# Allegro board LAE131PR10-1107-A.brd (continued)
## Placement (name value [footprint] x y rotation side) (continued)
PC106  -  [C_0805]  227.23 28.96 90 bottom
PC107  -  [C_0805]  227.21 28.96 90 top
PC108  -  [C_0805]  223.8 28.96 90 bottom
PC109  -  [C_0805]  225.52 28.96 90 bottom
PC110  -  [C_0805]  225.49 28.96 90 top
PC111  -  [C_0603]  232.5 21.71 0 bottom
PC112  -  [C_0603]  230.23 26.03 90 top
PC113  -  [C_0402]  235.83 22.95 270 bottom
PC114  -  [C_0603]  39.54 48.04 180 bottom
PC115  -  [C_0402]  38.09 45.33 0 bottom
PC116  -  [C_0402]  38.09 45.33 0 top
PC117  -  [C_0805]  37.12 42.51 180 top
PC118  -  [C_0805]  37.09 42.56 180 bottom
PC119  -  [C_0603]  32.13 49.03 180 bottom
PC120  -  [C_0805]  39.12 55.42 0 bottom
PC121  -  [C_0805]  39.17 53.71 0 top
PC122  -  [C_0805]  39.12 55.42 0 top
PC123  -  [C_0805]  39.14 57.17 0 bottom
PC124  -  [C_0805]  39.17 53.71 0 bottom
PC125  -  [C_0603]  36.76 47.54 0 top
PC126  -  [C_0603]  32.16 47.82 180 bottom
PC127  -  [C_0402]  32.29 45.93 180 bottom
PC128  -  [C_0402]  238.44 23.73 270 bottom
PC129  -  [C_0805]  223.78 28.96 90 top
PC130  -  [C_0805]  39.14 57.17 0 top
PC200  -  [C_0805]  35.18 38.6 0 bottom
PC201  -  [C_0805]  35.19 39.25 0 top
PC202  -  [C_0402]  35.08 40.56 0 top
PC203  -  [C_0402]  30.36 38.59 270 bottom
PC204  -  [C_0603]  30.3 26.46 270 bottom
PC205  -  [C_0603]  30.69 31.73 0 bottom
PC206  -  [C_0402]  32.81 34.08 180 bottom
PC207  -  [C_0402]  32.81 34.97 180 bottom
PC208  -  [C_0402]  31.98 35.86 0 bottom
PC209  -  [C_0603]  39.13 27.73 0 bottom
PC210  -  [C_0603]  39.11 25.28 0 bottom
PC211  -  [C_0603]  39.11 25.29 0 top
PC212  -  [C_0603]  39.11 26.5 0 top
PC213  -  [C_0603]  39.13 26.5 0 bottom
PC214  -  [C_0603]  38.23 32.39 0 bottom
PC216  -  [C_0402]  39.59 23.25 0 top
PC217  -  [C_0402]  39.59 24.14 0 top
PC218  -  [C_0402]  38.15 33.27 270 top
PC219  -  [C_0603]  38.23 33.61 0 bottom
PC221  -  [C_0402]  39.08 39.54 0 top
PC222  -  [C_0402]  40.07 35.74 270 top
PC301  -  [C_0402]  181.04 103.31 180 bottom
PC302  -  [C_0603]  181.66 95.83 90 top
PC303  -  [C_0402]  181.04 102.42 180 bottom
PC304  -  [C_0603]  185.8 100.94 180 top
PC305  -  [C_0603]  181.73 101.36 270 bottom
PC306  -  [C_0603]  181.74 101.38 270 top
PC307  -  [C_0402]  188.48 98.34 180 bottom
PC308  -  [C_0603]  178.09 98.43 90 top
PC309  -  [C_0603]  179.95 98.42 90 bottom
PC310  -  [C_0603]  179.97 98.42 90 top
PC311  -  [C_0603]  178.18 98.42 90 bottom
PC312  -  [C_0603]  186.06 102.55 90 bottom
PC313  -  [C_0603]  185.8 98.46 270 top
PC401  -  [C_0402]  181 113.01 180 bottom
PC402  -  [C_0402]  189.94 109.68 0 bottom
PC403  -  [C_0603]  188.18 107.02 180 bottom
PC404  -  [C_0603]  189.04 110.84 180 top
PC406  -  [C_0603]  181.87 107.65 0 bottom
PC407  -  [C_0603]  181.89 106.41 0 bottom
PC408  -  [C_0402]  188.19 105.96 180 bottom
PC409  -  [C_0402]  188.74 111.92 180 top
PC410  -  [C_0402]  186.95 114.18 180 bottom
PC411  -  [C_0402]  177.7 113.32 0 bottom
PC412  -  [C_0603]  175.74 113.28 270 bottom
PC413  -  [C_0603]  175.74 113.28 270 top
PC415  -  [C_0603]  174.16 106.9 0 bottom
PC416  -  [C_0603]  174.13 105.63 0 bottom
PC417  -  [C_0402]  176.82 113.29 270 bottom
PC418  -  [C_0402]  176.82 113.29 270 top
PC419  -  [C_0402]  168.98 106.72 90 bottom
PC420  -  [C_0402]  168.66 111.87 270 bottom
PC422  -  [C_0603]  181.85 108.88 0 bottom
PC424  -  [C_0603]  174.16 108.21 0 bottom
PC501  -  [C_0603]  159.84 101.85 180 bottom
PC502  -  [C_0603]  166.55 103.78 0 bottom
PC503  -  [C_0402]  168.91 99.47 90 bottom
PC504  -  [C_0603]  159.84 103.14 180 bottom
PC505  -  [C_0402]  164.84 99.07 270 bottom
PC506  -  [C_0402]  163.92 99.65 90 bottom
PC513  -  [C_0402]  199.9 22.8 0 top
PC514  -  [C_0603]  199.81 25.75 180 top
PC515  -  [C_0402]  194.17 23.48 270 top
PC516  -  [C_0603]  195.21 25.85 0 top
PC601  -  [C_0402]  55.12 78.1 180 top
PC602  -  [C_0402]  49.15 71.21 0 bottom
PC603  -  [C_0603]  50.17 72.36 0 bottom
PC604  -  [C_0603]  48.38 73.46 90 bottom
PC605  -  [C_0402]  51.93 66.24 270 top
PC606  -  [C_D]  68.07 79.65 90 bottom
PC608  -  [C_0805]  74.67 89.6 270 bottom
PC611  -  [C_0603]  73.29 89.85 180 top
PC612  -  [C_0805]  74.67 89.6 270 top
PC613  -  [C_0402]  50.34 69.79 270 bottom
PC614  -  [C_0402]  53.47 69.56 270 bottom
PC616  -  [C_0402]  51.61 69.41 270 bottom
PC617  -  [C_0402]  49.89 65.3 0 bottom
PC618  -  [C_0402]  48.01 65.12 0 top
PC619  -  [C_0402]  48.01 64.1 0 top
PC620  -  [C_0402]  49.02 65.32 180 bottom
PC621  -  [C_0402]  46.99 64.23 90 top
PC622  -  [C_0603]  77.6 87.72 180 top
PC624  -  [C_0402]  53.6 67.01 270 bottom
PC625  -  [C_0402]  54.74 70.33 0 bottom
PC626  -  [C_0402]  52.68 67.01 270 bottom
PC627  -  [C_0402]  53.71 66.2 90 top
PC628  -  [C_0402]  52.38 74.62 270 bottom
PC629  -  [C_0402]  55.23 73.92 270 bottom
PC630  -  [C_0402]  56.95 75.55 90 top
PC631  -  [C_0402]  50.55 73.75 0 bottom
PC632  -  [C_0402]  51.18 76.24 90 top
PC633  -  [C_0402]  51.17 76.31 90 bottom
PC635  -  [C_0402]  57.91 67.54 180 top
PC636  -  [C_0402]  54.78 71.2 0 bottom
PC637  -  [C_0402]  49.39 76.31 90 bottom
PC638  -  [C_0402]  57.35 68.46 90 top
PC639  -  [C_0402]  57.89 72.89 0 top
PC640  -  [C_0402]  53.28 77.59 180 top
PC641  -  [C_0402]  50.87 66.17 180 bottom
PC642  -  [C_0402]  56.94 76.45 0 bottom
PC643  -  [C_0402]  53.27 74.62 270 bottom
PC644  -  [C_0402]  49.41 78.2 180 bottom
PC645  -  [C_0402]  79 79.8 180 top
PC646  -  [C_0402]  56.94 75.56 0 bottom
PC647  -  [C_0402]  59.73 72.02 270 top
PC649  -  [C_0402]  54.23 76.68 0 bottom
PC650  -  [C_0402]  52.49 76.7 0 bottom
PC651  -  [C_0402]  58.74 73.78 180 top
PC652  -  [C_0402]  52.49 77.59 0 bottom
PC653  -  [C_0402]  56.95 73.77 90 top
PC654  -  [C_0402]  58.74 74.67 180 top
PC655  -  [C_0603]  76.46 76.31 90 top
PC656  -  [C_0805]  69.41 78.05 90 top
PC657  -  [C_0805]  71.31 78.05 90 top
PC658  -  [C_0805]  71.31 78.05 90 bottom
PC659  -  [C_0402]  64.84 77.29 270 top
PC660  -  [C_0402]  63.95 77.29 270 top
PC661  -  [C_0402]  77.4 84.8 0 top
PC662  -  [C_0603]  69.62 84.08 270 top
PC663  -  [C_0603]  54.66 67.53 0 bottom
PC664  -  [C_0805]  56.68 60.93 0 bottom
PC665  -  [C_0805]  56.68 62.71 0 bottom
PC669  -  [C_0402]  62.37 68.98 0 bottom
PC670  -  [C_0603]  64.39 61.18 180 bottom
PC671  -  [C_0603]  62.79 75.17 0 top
PC672  -  [C_0805]  65.47 70.69 0 top
PC673  -  [C_0805]  65.47 70.69 0 bottom
PC677  -  [C_0402]  70.68 76.93 0 bottom
PC678  -  [C_0603]  69.26 72.17 90 top
PC679  -  [C_0402]  63.57 71.15 270 bottom
PC680  -  [C_0402]  62.15 77.28 270 top
PC681  -  [C_0402]  55.12 64.43 270 bottom
PC682  -  [C_0805]  61.69 77.88 180 bottom
PC683  -  [C_0805]  61.77 72.38 270 bottom
PC684  -  [C_0805]  60.02 72.41 270 bottom
PC685  -  [C_0402]  72.99 86.38 0 bottom
PC686  -  [C_0402]  63.04 77.29 270 top
PC687  -  [C_0402]  54.1 64.43 270 bottom
PC688  -  [C_0402]  64.45 71.15 270 bottom
PC902  -  [C_0402]  50.94 80.49 270 top
PC903  -  [C_0402]  50.56 80.41 270 bottom
PC904  -  [C_0805]  56.37 78.8 0 top
PC905  -  [C_0805]  56.37 78.8 0 bottom
PC906  -  [C_0805]  56.39 80.54 0 top
PC909  -  [C_B2]  45.27 79.69 0 bottom
PC910  -  [C_B2]  45.38 76.49 0 bottom
PC911  -  [C_0805]  53.52 78.89 180 bottom
PC913  -  [C_0805]  67.95 91.66 0 bottom
PC914  -  [C_0805]  67.95 91.66 0 top
PC915  -  [C_0805]  69.7 93.47 0 bottom
PC916  -  [C_0805]  67.95 88.17 0 top
PC917  -  [C_0805]  67.92 89.95 0 top
PC918  -  [C_0805]  67.95 88.19 0 bottom
PC919  -  [C_0805]  65.22 92.68 180 top
PC920  -  [C_0805]  67.93 89.91 0 bottom
PC925  -  [C_0402]  58.73 88.36 0 bottom
PC926  -  [C_0402]  57.41 89.34 180 bottom
PC927  -  [C_0402]  60.51 88.36 270 bottom
PC928  -  [C_0402]  69.65 94.82 0 bottom
PC929  -  [C_0402]  69.65 94.82 0 top
PC930  -  [C_0603]  63.88 87.2 90 bottom
PC931  -  [C_0603]  55.7 91.62 0 bottom
PC932  -  [C_0402]  65.85 88.29 180 bottom
PC933  -  [C_0402]  57.34 91.8 180 top
PC934  -  [C_0603]  66.9 91.5 180 bottom
PC935  -  [C_0805]  202.69 39.21 90 bottom
PC936  -  [C_0805]  200.92 39.21 90 bottom
PC937  -  [C_0402]  208.28 42.04 180 bottom
PC938  -  [C_0402]  56.95 96.19 90 bottom
PC939  -  [C_0402]  64.92 93.43 0 bottom
PC940  -  [C_0603]  52.52 89.82 0 top
PC941  -  [C_0603]  60.67 77.6 180 top
PC942  -  [C_0402]  64.94 94.35 0 bottom
PC943  -  [C_0402]  60.69 96.09 180 bottom
PC944  -  [C_0402]  60.69 96.97 180 bottom
PC945  -  [C_0402]  64.76 95.41 0 bottom
PC946  -  [C_0402]  64.75 96.36 90 bottom
PC947  -  [C_0402]  61.45 95.64 90 top
PC949  -  [C_0402]  31.8 73.73 0 top
PC950  -  [C_0402]  62.96 96.89 270 bottom
PC951  -  [C_B2]  45.25 82.88 0 bottom
PC1001  -  [C_0603]  123.13 81.82 270 top
PC1002  -  [C_0603]  120.7 75.66 90 top
PC1003  -  [C_0603]  86.69 84.27 270 bottom
PC1004  -  [C_0603]  121.92 75.66 90 top
PC1005  -  [C_0603]  89.1 84.27 270 bottom
PC1006  -  [C_0603]  125.54 75.66 90 top
PC1007  -  [C_0603]  87.9 84.3 270 top
PC1008  -  [C_0603]  85.46 84.27 270 top
PC1009  -  [C_0603]  124.86 95.23 90 top
PC1010  -  [C_0603]  120.73 79.44 270 top
PC1011  -  [C_0603]  88.85 81.18 270 bottom
PC1012  -  [C_0603]  86.44 81.17 270 bottom
PC1013  -  [C_0603]  124.33 75.66 90 top
PC1014  -  [C_0603]  115.38 77.31 90 top
PC1015  -  [C_0603]  118.26 72.71 0 top
PC1016  -  [C_0603]  112.17 72.74 0 top
PC1017  -  [C_0603]  86.87 77.77 270 bottom
PC1018  -  [C_0603]  115.67 72.76 0 top
PC1019  -  [C_0603]  113.22 80.61 180 top
PC1020  -  [C_0603]  117.81 81.07 270 top
PC1021  -  [C_0603]  116.61 81.07 270 top
PC1022  -  [C_0603]  104.88 80.33 90 top
PC1023  -  [C_0603]  114.15 74.95 90 top
PC1024  -  [C_0603]  116.59 77.33 90 top
PC1025  -  [C_0603]  89.22 77.76 270 top
PC1026  -  [C_0603]  115.38 81.06 270 top
PC1027  -  [C_0603]  105.23 82.72 90 top
PC1028  -  [C_0603]  115.38 74.96 90 top
PC1029  -  [C_0603]  104.02 82.71 90 top
PC1030  -  [C_0201]  119.77 77.08 180 top
PC1031  -  [C_0201]  126.95 81.14 0 top
PC1032  -  [C_0201]  126.95 80.57 0 top
PC1033  -  [C_0201]  126.64 84.19 0 top
PC1034  -  [C_0201]  119.79 77.67 180 top
PC1035  -  [C_0201]  119.75 79.96 180 top
PC1036  -  [C_0201]  127.84 84.29 0 top
PC1037  -  [C_0201]  120.42 82.86 180 top
PC1038  -  [C_0201]  126.38 74.74 180 top
PC1039  -  [C_0201]  119.8 75.29 180 top
PC1040  -  [C_0201]  107.82 78.61 270 top
PC1041  -  [C_0201]  106.61 76.77 0 top
PC1042  -  [C_0201]  114.03 84.16 0 top
PC1043  -  [C_0201]  105.86 77.78 270 top
PC1044  -  [C_0201]  106.51 79.92 90 top
PC1045  -  [C_0201]  114.5 73.05 270 top
PC1046  -  [C_0201]  110.54 83.48 270 top
PC1047  -  [C_0201]  106.51 78.52 90 top
PC1048  -  [C_0201]  108.46 81.34 270 top
PC1049  -  [C_0201]  113.41 84.14 180 top
PC1050  -  [C_0201]  126.95 78.28 0 top
PC1051  -  [C_0201]  126.05 84.18 180 top
PC1052  -  [C_0201]  126.95 79.43 0 top
PC1053  -  [C_0201]  122 74.03 270 top
PC1054  -  [C_0201]  122.63 73.6 270 top
PC1055  -  [C_0201]  107.8 79.96 90 top
PC1056  -  [C_0201]  113.93 81.86 0 top
PC1057  -  [C_0603]  130.34 79.57 180 top
PC1058  -  [C_0603]  88.99 88.5 90 bottom
PC1059  -  [C_0603]  88.99 87.47 270 bottom
PC1060  -  [C_0603]  129.2 84.14 0 top
PC1061  -  [C_0603]  86.41 81.17 270 top
PC1062  -  [C_D3]  120.53 95.98 90 top
PC1063  -  [C_D2]  82.11 67.91 270 bottom
PC1064  -  [C_0603]  123.64 95.22 90 top
PC1065  -  [C_0603]  89.12 84.3 270 top
PC1066  -  [C_0603]  125.64 81.85 270 top
PC1067  -  [C_0603]  126.08 95.24 90 top
PC1068  -  [C_0603]  123.17 79.46 270 top
PC1069  -  [C_0603]  124.37 79.46 270 top
PC1070  -  [C_0603]  125.58 79.46 270 top
PC1071  -  [C_0603]  123.13 75.66 90 top
PC1072  -  [C_0603]  121.96 79.46 270 top
PC1073  -  [C_0603]  120.68 81.81 270 top
PC1074  -  [C_0603]  85.46 84.27 270 bottom
PC1075  -  [C_0603]  124.37 81.83 270 top
PC1076  -  [C_0603]  121.9 81.8 270 top
PC1077  -  [C_0603]  88.85 81.18 270 top
PC1078  -  [C_0603]  87.64 81.18 270 top
PC1079  -  [C_0603]  86.69 84.27 270 top
PC1080  -  [C_0603]  87.64 81.18 270 bottom
PC1081  -  [C_0603]  85.19 81.2 270 top
PC1082  -  [C_0603]  87.9 84.27 270 bottom
PC1083  -  [C_0201]  123.65 84.16 180 top
PC1084  -  [C_0201]  124.27 84.17 0 top
PC1085  -  [C_0201]  126.95 76 0 top
PC1086  -  [C_0201]  119.8 74.72 180 top
PC1087  -  [C_0201]  123.18 74.78 0 top
PC1088  -  [C_0201]  126.95 81.71 0 top
PC1089  -  [C_0201]  126.95 82.28 0 top
PC1090  -  [C_0201]  126.95 80 0 top
PC1091  -  [C_0201]  126.95 77.14 0 top
PC1092  -  [C_0201]  126.95 77.71 0 top
PC1093  -  [C_0201]  126.95 78.86 0 top
PC1094  -  [C_0201]  119.75 81.13 180 top
PC1095  -  [C_0201]  119.75 81.7 180 top
PC1096  -  [C_0201]  119.75 82.27 180 top
PC1097  -  [C_0201]  128.33 83.66 270 top
PC1098  -  [C_0201]  119.75 80.53 180 top
PC1099  -  [C_0201]  119.77 76.51 180 top
PC1100  -  [C_0603]  85.73 72.04 270 bottom
PC1101  -  [C_0603]  84.52 72.04 270 top
PC1102  -  [C_0603]  89.24 74.77 270 top
PC1103  -  [C_0603]  87 72.04 270 top
PC1125  -  [C_0201]  119.8 75.86 180 top
PC1126  -  [C_0201]  126.95 76.57 0 top
PC1127  -  [C_D3]  103.28 97.55 180 top
PC1128  -  [C_D3]  84.39 67.91 270 top
PC1129  -  [C_0603]  104.86 78.09 270 top
PC1130  -  [C_0603]  104.27 74.26 90 top
PC1131  -  [C_0603]  103.36 78.07 270 top
PC1132  -  [C_0603]  101.73 78.07 270 top
PC1133  -  [C_0603]  88.09 77.76 270 bottom
PC1134  -  [C_0603]  117.79 77.33 90 top
PC1135  -  [C_0603]  101.8 80.33 90 top
PC1136  -  [C_0603]  88.01 77.76 270 top
PC1137  -  [C_0603]  89.3 77.76 270 bottom
PC1138  -  [C_0603]  103.31 80.35 90 top
PC1139  -  [C_0603]  88.99 87.48 270 top
PC1140  -  [C_0603]  87.72 88.51 90 top
PC1141  -  [C_0603]  88.99 88.5 90 top
PC1142  -  [C_0603]  132.1 75.11 0 top
PC1143  -  [C_0603]  131.15 75.11 180 top
PC1144  -  [C_0603]  130.34 80.78 180 top
PC1145  -  [C_0603]  87.72 87.46 270 bottom
PC1146  -  [C_0603]  87.72 88.51 90 bottom
PC1147  -  [C_0201]  131.17 81.52 0 top
PC1148  -  [C_0201]  131 78.54 180 top
PC1149  -  [C_0201]  129.8 82.3 0 top
PC1150  -  [C_0201]  129.8 81.73 0 top
PC1151  -  [C_0201]  129.18 82.3 180 top
PC1152  -  [C_0201]  129.18 81.73 180 top
PC1153  -  [C_0201]  132.25 78.53 270 top
PC1164  -  [C_0201]  119.79 78.28 180 top
PC1165  -  [C_D2]  77.22 67.91 270 bottom
PC1170  -  [C_0603]  85.22 81.17 270 bottom
PC1171  -  [C_0603]  90.55 82.33 270 bottom
PC1172  -  [C_0603]  94.36 82.33 270 bottom
PC1173  -  [C_0603]  93.09 82.33 270 bottom
PC1174  -  [C_0603]  91.82 82.33 270 bottom
PC1175  -  [C_0603]  83.16 74.8 270 top
PC1176  -  [C_0603]  84.38 74.77 270 top
PC1177  -  [C_0603]  85.57 74.77 270 bottom
PC1178  -  [C_0603]  84.36 74.77 270 bottom
PC1179  -  [C_0603]  83.29 72.05 270 top
PC1180  -  [C_0603]  84.48 72.05 270 bottom
PC1181  -  [C_0603]  84.46 77.77 270 bottom
PC1182  -  [C_0603]  92.27 78.14 270 bottom
PC1183  -  [C_0603]  86.81 74.77 270 top
PC1184  -  [C_0603]  88.28 72.03 270 top
PC1185  -  [C_0603]  91 78.14 270 bottom
PC1186  -  [C_0603]  88.01 74.77 270 bottom
PC1187  -  [C_0603]  88.28 72.02 270 bottom
PC1188  -  [C_0603]  85.6 74.77 270 top
PC1189  -  [C_0603]  85.65 77.77 270 bottom
PC1190  -  [C_0603]  85.73 72.04 270 top
PC1191  -  [C_0603]  83.21 72.08 270 bottom
PC1192  -  [C_0603]  86.81 77.76 270 top
PC1193  -  [C_0603]  85.6 77.76 270 top
PC1194  -  [C_0603]  88.01 74.78 270 top
PC1195  -  [C_0603]  90.97 78.11 90 top
PC1196  -  [C_0603]  93.54 78.14 270 bottom
PC1197  -  [C_0603]  86.81 74.77 270 bottom
PC1198  -  [C_0603]  87 72.04 270 bottom
PC1199  -  [C_0603]  89.22 74.77 270 bottom
PC1201  -  [C_0402]  37.72 75.3 0 top
PC1202  -  [C_0603]  46.14 104.94 270 top
PC1203  -  [C_0402]  53.79 95.79 0 top
PC1204  -  [C_0402]  48.52 75.53 0 top
PC1205  -  [C_0402]  37.92 67.82 270 top
PC1206  -  [C_0402]  39.63 66.94 0 top
PC1207  -  [C_0402]  34.43 67.8 270 top
PC1208  -  [C_0402]  17.78 98.06 180 bottom
PC1209  -  [C_0402]  24.89 99.03 270 bottom
PC1210  -  [C_0402]  53.07 105.91 270 top
PC1211  -  [C_0402]  41 71.2 180 bottom
PC1212  -  [C_0402]  38.29 72.13 270 bottom
PC1213  -  [C_0402]  40.95 72.09 180 bottom
PC1214  -  [C_0402]  42.73 71.47 270 bottom
PC1215  -  [C_0402]  13.93 93.44 180 bottom
PC1216  -  [C_0402]  41.78 69.45 0 bottom
PC1217  -  [C_0402]  37.77 91.75 0 top
PC1286  -  [C_0402]  56.95 92.63 90 bottom
PC1301  -  [C_0402]  46.08 60.72 180 top
PC1302  -  [C_0402]  45.51 57.63 180 top
PC1303  -  [C_0805]  48.73 55.28 0 top
PC1304  -  [C_0805]  48.73 53.56 0 top
PC1305  -  [C_0603]  56.45 59.11 270 top
PC1306  -  [C_0603]  58.93 59.11 270 top
PC1307  -  [C_0603]  57.72 59.11 270 top
PC1308  -  [C_0402]  46.08 61.61 180 top
PC1309  -  [C_0402]  52.33 54.79 180 top
PC1310  -  [C_0402]  51.06 61.61 90 top
PC1311  -  [C_0402]  44.93 43.71 180 top
PC1312  -  [C_0805]  46.85 42.42 0 top
PC1313  -  [C_0805]  46.85 44.14 0 top
PC1314  -  [C_0603]  57.37 50.23 270 top
PC1315  -  [C_0603]  54.89 50.24 270 top
PC1316  -  [C_0603]  56.12 50.26 270 top
PC1317  -  [C_0402]  45.51 48.57 180 top
PC1318  -  [C_0402]  45.51 49.46 180 top
PC1319  -  [C_0402]  50.94 43.47 180 top
PC1320  -  [C_0402]  48.55 50.46 90 top
PD1  -  [TVNST52302AB0_SOT523-3]  210.61 25.99 180 top
PD2  -  [TVNST52302AB0_SOT523-3]  212.64 25.99 180 top
PD3  -  [DB3J315E0L_SMINI3-F2-B3]  308.94 10.52 180 top
PD4  -  [PESD5V0U2BT_SOT23-3]  52.83 104.26 270 bottom
PD5  -  [PDS5100H-13_POWERDI5-3]  51.91 90.35 90 bottom
PD100  -  [RB520SM-30T2R_EMD2-2]  32.07 44.04 180 bottom
PD901  -  [SDMK0340L-7-F_SOD323-2]  68.48 102.6 270 bottom
PD903  -  [RB520SM-30T2R_EMD2-2]  66.72 102.53 270 bottom
PD904  -  [SDMK0340L-7-F_SOD323-2]  64.99 102.48 270 bottom
PD905  -  [BAT54CW_SOT323-3]  30.21 73.77 270 top
PD1202  -  [PDS5100H-13_POWERDI5-3]  48.87 96.09 90 top
PD1205  -  [SDMK0340L-7-F_SOD323-2]  41.09 73.89 180 bottom
PD1801  -  [BAT54CW_SOT323-3]  36.45 74.52 180 bottom
PH601  -  [R_0402]  68.22 71.1 0 bottom
PH602  -  [R_0402]  71.99 70.81 180 bottom
PH603  -  [R_0402]  74.12 76.29 180 top
PH604  -  [R_0402]  83.97 91.12 0 bottom
PH605  -  [R_0402]  73.87 78.28 180 bottom
PJP1  -  [JUMP_43X39]  128.84 109.63 270 bottom
PJP2  -  [JUMP_43X39]  130.94 97.88 90 bottom
PJP3  -  [JUMP_43X118]  142.37 103.41 0 bottom
PJP4  -  [JUMP_43X39]  165.86 60.17 0 top
PJP5  -  [JUMP_43X79]  17.29 82.04 180 top
PJP6  -  [JUMP_43X39]  25.91 74.01 180 top
PJP7  -  [JUMP_43X39]  31.69 69.83 270 top
PJP8  -  [JUMP_43X79]  18.12 58.77 0 bottom
PJP12  -  [JUMP_43X39]  70.8 114.31 270 top
PJP14  -  [JUMP_43X79]  294.66 45.43 0 top
PJP15  -  [JUMP_43X39]  298.59 18.57 180 top
PJP16  -  [JUMP_43X39]  291.38 20.6 180 top
PJP17  -  [JUMP_43X79]  299.55 21.62 0 top
PJP18  -  [JUMP_43X39]  291.38 23.07 180 top
PJP19  -  [JUMP_43X39]  308.76 31.92 45 top
PJP20  -  [JUMP_43X39]  276.04 37.81 180 top
PJP21  -  [JUMP_43X39]  276.04 40.1 180 top
PJP22  -  [JUMP_43X39]  266.45 30.45 90 top
PJP31  -  [JUMP_43X118]  30.48 17.58 90 top
PJP35  -  [JUMP_43X39]  246.57 24.67 0 top
PJP36  -  [JUMP_43X79]  296.72 62.01 180 top
PJP37  -  [JUMP_43X39]  304.29 63.9 90 top
PJP38  -  [JUMP_43X39]  198.45 31.39 270 top
PJP39  -  [JUMP_43X118]  197.97 41.28 180 top
PJP40  -  [JUMP_43X79]  288.9 83.42 90 top
PJP41  -  [JUMP_43X118]  286.46 72.15 180 top
PJP42  -  [JUMP_43X39]  166.05 69.69 90 top
PJP100  -  [JUMP_43X79]  236.73 31.7 270 bottom
PJP101  -  [JUMP_43X79]  39.88 42.94 180 bottom
PJP102  -  [JUMP_43X118]  221.97 23.95 180 top
PJP103  -  [JUMP_43X118]  38.8 59.36 90 bottom
PJP200  -  [JUMP_43X118]  40.52 28.94 90 top
PJP201  -  [JUMP_43X39]  38.47 35.35 0 bottom
PJP202  -  [JUMP_43X79]  32.7 40.32 270 bottom
PJP301  -  [JUMP_43X79]  183.45 104.27 270 bottom
PJP302  -  [JUMP_43X118]  180.5 95.13 180 bottom
PJP391  -  [JUMP_43X39]  168.39 89.63 0 bottom
PJP401  -  [JUMP_43X79]  180.23 107.65 180 bottom
PJP402  -  [JUMP_43X79]  175.21 103.8 270 bottom
PJP403  -  [JUMP_43X39]  190.44 107.85 180 bottom
PJP404  -  [JUMP_43X39]  173.67 115.49 270 bottom
PJP501  -  [JUMP_43X39]  170.13 102.89 180 bottom
PJP502  -  [JUMP_43X39]  160.68 100.19 270 bottom
PJP505  -  [JUMP_43X39]  199.52 28.23 270 top
PJP506  -  [JUMP_43X39]  193.42 24.62 90 top
PJP601  -  [JUMP_43X118]  65.95 80.34 180 top
PJP602  -  [JUMP_43X79]  62.99 74.11 90 bottom
PJP603  -  [JUMP_43X39]  77.73 91.03 90 bottom
PJP901  -  [JUMP_43X118-NPM]  53.3 84.07 270 bottom
PJP1202  -  [JUMP_43X118]  46.2 108.11 270 top
PJP1301  -  [JUMP_43X39]  44.9 59.16 0 top
PJP1302  -  [JUMP_43X79]  57.6 60.83 90 top
PJP1303  -  [JUMP_43X79]  56.12 51.88 90 top
PJP1304  -  [JUMP_43X39]  44.3 47.03 0 top
PJPDC1  -  [CVILU_CI0805M1HRC-NH_5P-T]  47.7 103.6 270 bottom
PL1  -  [TAIYO_FBMJ4516HS720NT_2P]  211.95 35.59 90 bottom
PL2  -  [TAIYO_FBMJ4516HS720NT_2P]  214.37 35.59 90 bottom
PL3  -  [MURAT_BLM15AG102SN1D_2P]  50.75 106.72 180 bottom
PL4  -  [TAIYO_FBMJ4516HS720NT_2P]  50.65 97.32 90 bottom
PL100  -  [CYNTE_PCMC063T-1R5MN_2P]  230.38 24.82 180 bottom
PL101  -  [CYNTE_PCMC063T-1R5MN_2P]  35.08 50.26 90 bottom
PL201  -  [CYNTE_PCMB063T-1R0MS_2P]  35.08 30.47 270 bottom
PL301  -  [MAG_MMD-05CZ-R68M-X2L_2P]  187.73 95.12 180 bottom
PL402  -  [MAG_MLV-FY12N1R0M-O1L_2P]  183.16 111.03 180 bottom
PL404  -  [MAG_MLV-FY12N1R0M-O1L_2P]  172.15 108.27 270 bottom
PL501  -  [MAG_MLV-FY12N1R0M-O1L_2P]  163.69 102.47 180 bottom
PL602  -  [9A_Z80_1812_2P-NPM]  67.3 80.32 180 top
PL610  -  [MAG_MMD06CZER15MG_4P]  82.52 81.35 180 bottom
PL612  -  [MAG_MMD06CZER15MG_4P]  80.52 73.75 180 bottom
PL613  -  [MAG_MMD06CZER15MG_4P]  72.39 66.01 180 bottom
PL614  -  [MAG_MMD05CZR47M_4P]  85.27 87.89 180 bottom
PL901  -  [MAGLA_MMD-05CZ-1R0M-M7L_2P]  53.34 81.43 90 bottom
PL902  -  [CYNTE_PCMB063T-1R0MS_2P]  57.79 83.18 0 bottom
PL1201  -  [5A_Z120_0805_2P]  17.69 94.83 0 bottom
PL1202  -  [5A_Z120_0805_2P]  17.69 96.49 0 bottom
PL1301  -  [MAG_MLV-FY12N1R0M-O1L_2P]  54.17 57.78 90 top
PL1302  -  [MAG_MLV-FY12N1R0M-O1L_2P]  52.71 46.77 90 top
PQ1  -  [DMN65D8LDW-7_SOT363-6]  39.98 105.38 90 top
PQ2  -  [FDV301N-G_SOT23-3]  33.16 100.85 90 top
PQ3  -  [MMST3904-7-F_SOT323-3]  29.31 102.66 0 top
PQ4  -  [AON7409_DFN8-5]  48.59 89.05 180 bottom
PQ5  -  [NTR4502PT1G_SOT23-3]  42.67 85.97 180 bottom
PQ6  -  [DMN65D8LW-7_SOT323-3]  58.65 100.95 0 bottom
PQ7  -  [DMN65D8LW-7_SOT323-3]  47.27 84.37 0 bottom
PQ8  -  [DMN65D8LW-7_SOT323-3]  30.23 106.25 180 top
PQ9  -  [AON7409_DFN8-5]  52.73 99.02 0 bottom
PQ501  -  [AON7934_DFN3X3A8-10]  76.42 89.55 0 bottom
PQ904  -  [AON6992_DFN5X6D-8-7]  66.4 84.02 90 top
PQ905  -  [AON6992_DFN5X6D-8-7]  52.72 86 270 top
PQ906  -  [AON7409_DFN8-5]  206.99 38.75 90 bottom
PQ909  -  [DMN65D8LW-7_SOT323-3]  61.62 99.8 0 bottom
PQ1201  -  [DMN65D8LDW-7_SOT363-6]  36.69 97.38 270 top
PQ1202  -  [AON7409_DFN8-5]  52.27 98.03 0 top
PQ1203  -  [NTR4502PT1G_SOT23-3]  45.16 76.53 0 top
PQ1204  -  [DMN65D8LDW-7_SOT363-6]  43.46 81.37 0 top
PQ1205  -  [DMN65D8LW-7_SOT323-3]  49.79 86.96 180 top
PQ1206  -  [AON7409_DFN8-5]  49.79 106.66 0 top
PQ1207  -  [DMN66D0LDW-7_SOT363-6]  47.06 92.03 180 top
PQ1208  -  [DMN66D0LDW-7_SOT363-6]  43.11 88.28 90 top
PQ1209  -  [DMN65D8LDW-7_SOT363-6]  45.63 72.36 270 bottom
PQ1210  -  [DMN66D0LDW-7_SOT363-6]  40.64 92.73 90 top
PQ1211  -  [DMN66D0LDW-7_SOT363-6]  42.61 91.67 0 top
PQ1212  -  [DMN65D8LW-7_SOT323-3]  42.17 73.5 90 top
PQ1213  -  [AON7409_DFN8-5]  49.65 104.8 180 top
PQ1214  -  [DMN65D8LDW-7_SOT363-6]  41.94 100.78 270 top
PQ1215  -  [NTR4502PT1G_SOT23-3]  38.1 103.45 180 top
PQ1216  -  [DMN65D8LW-7_SOT323-3]  39.37 89.37 180 bottom
PR1  -  [R_0402]  209.23 28.54 0 top
PR2  -  [R_0402]  310.78 11.28 90 top
PR3  -  [R_0402]  33.05 98.48 180 top
PR4  -  [R_0402]  29.36 98.38 90 top
PR5  -  [R_0402]  31.31 98.48 180 top
PR6  -  [R_0402]  34.04 98.52 90 top
PR7  -  [R_0402]  29.34 100.68 90 top
PR8  -  [R_0402]  28.34 105.64 0 top
PR10  -  [R_0402]  43.72 89.76 180 bottom
PR11  -  [R_0402]  45.09 87.14 270 bottom
PR12  -  [R_0402]  55.76 102.46 0 bottom
PR13  -  [R_0805]  54.13 100.97 90 bottom
PR14  -  [R_0402]  43.72 90.65 180 bottom
PR15  -  [R_0402]  35.67 109.91 0 top
PR16  -  [R_0402]  44.68 85.16 0 bottom
PR17  -  [R_0402]  39.12 107.82 0 top
PR18  -  [R_0402]  56.14 99.66 0 bottom
PR19  -  [R0402_0OHM]  41 107.03 90 top
PR20  -  [R0402_0OHM]  48.05 83.24 180 bottom
PR21  -  [R0402_0OHM]  28.92 111.2 0 top
PR22  -  [R0402_0OHM]  34.78 108.4 180 top
PR23  -  [R0402_0OHM]  33.92 109.37 0 top
PR24  -  [R_0402]  47.12 82.34 0 bottom
PR25  -  [R0402_0OHM]  36.59 110.82 180 top
PR26  -  [R0402_0OHM]  33.25 106.38 0 top
PR27  -  [R_0402]  34.16 107.25 180 top
PR28  -  [R_0402]  31.98 106.6 90 top
PR29  -  [R0402_0OHM]  31.98 108.43 0 top
PR100  -  [R0603_0OHM]  231.73 30.16 180 bottom
PR102  -  [R_0402]  30.66 42.92 270 bottom
PR103  -  [R_0402]  29.3 43.38 90 bottom
PR104  -  [R0402_0OHM]  232.67 24.02 0 bottom
PR105  -  [R0402_0OHM]  232.67 23 0 bottom
PR106  -  [R_1206]  231.17 22.05 90 top
PR107  -  [R_0402]  238.39 25.61 180 bottom
PR108  -  [R_0402]  234.93 22.03 90 bottom
PR111  -  [R0603_0OHM]  38.15 46.78 0 bottom
PR112  -  [R_1206]  35.23 50.23 270 top
PR113  -  [R_0402]  31.52 42 90 bottom
PR114  -  [R0402_0OHM]  31.12 45.07 0 bottom
PR116  -  [R_0402]  237.49 23.73 270 bottom
PR117  -  [R_0402]  31.5 46.79 180 bottom
PR119  -  [R0402_0OHM]  237.48 24.67 0 bottom
PR120  -  [R0402_0OHM]  32.4 42.92 270 bottom
PR202  -  [R_1206]  30.56 30.4 270 bottom
PR203  -  [R0603_0OHM]  32.81 33 180 bottom
PR204  -  [R_0402]  31.94 36.75 0 bottom
PR205  -  [R_0402]  32.86 36.67 180 top
PR206  -  [R_0402]  32.87 37.61 180 bottom
PR207  -  [R_0402]  31.96 37.53 0 top
PR208  -  [R0402_0OHM]  39.98 37.74 180 top
PR209  -  [R_0402]  39.08 38.63 0 top
PR210  -  [R0402_0OHM]  39.18 34.82 90 top
PR212  -  [R_0402]  40.96 35.73 270 top
PR302  -  [R_0402]  191.58 95.26 180 bottom
PR303  -  [R_1206]  183.31 97.07 270 top
PR304  -  [R0603_0OHM]  183.32 100.58 270 top
PR306  -  [R_0402]  188.54 99.26 90 bottom
PR307  -  [R_0402]  191.51 97.25 180 bottom
PR308  -  [R_0402]  187.64 99.27 90 bottom
PR310  -  [R_0402]  190.59 98.14 0 bottom
PR311  -  [R_0402]  187.64 101.03 90 bottom
PR312  -  [R0402_0OHM]  191.53 96.26 180 bottom
PR402  -  [R0402_0OHM]  190.85 110.56 180 bottom
PR403  -  [R_0402]  189.96 111.45 0 bottom
PR404  -  [R_0402]  184.27 106.1 90 bottom
PR405  -  [R_0603]  183.34 113.14 180 bottom
PR406  -  [R0402_0OHM]  178.62 112.38 180 bottom
PR407  -  [R_0402]  177.74 114.19 0 bottom
PR408  -  [R_0402]  170.12 116.92 0 bottom
PR409  -  [R_0603]  170.06 108.21 270 bottom
PR410  -  [R_0402]  177.26 110.95 180 bottom
PR411  -  [R_0402]  168.7 112.71 0 bottom
PR412  -  [R_0402]  181.62 114.37 0 bottom
PR413  -  [R_0402]  188.75 114.2 270 bottom
PR414  -  [R_0402]  190.36 114.23 270 bottom
PR415  -  [R_0402]  187.84 113.29 90 bottom
PR416  -  [R_0402]  191.28 113.32 90 bottom
PR417  -  [R_0402]  170.04 114.24 0 bottom
PR418  -  [R_0402]  170.12 115.12 0 bottom
PR419  -  [R_0402]  169.61 112.71 180 top
PR420  -  [R_0402]  171.03 116.01 180 bottom
PR421  -  [R_0402]  184.24 113.3 0 bottom
PR422  -  [R_0402]  185.17 114.39 180 bottom
PR423  -  [R0402_0OHM]  168.68 110.1 270 bottom
PR424  -  [R_0402]  169.57 110.12 270 bottom
PR425  -  [R0402_0OHM]  185.17 106.11 90 bottom
PR426  -  [R0402_0OHM]  177.27 110.05 180 bottom
PR427  -  [R_0402]  186.92 113.29 180 bottom
PR428  -  [R_0402]  169.59 111.87 270 bottom
PR501  -  [R_0402]  169.8 99.47 90 bottom
PR502  -  [R_0603]  162.83 100.46 270 bottom
PR504  -  [R0402_0OHM]  166.66 98.13 90 bottom
PR505  -  [R_0402]  165.75 99.07 270 bottom
PR506  -  [R_0402]  170.69 100.39 270 bottom
PR513  -  [R0402_0OHM]  200.83 23.72 180 top
PR514  -  [R_0402]  199.94 21.9 0 top
PR515  -  [R_0402]  193.22 23.48 270 top
PR516  -  [R_0402]  193.23 21.68 0 top
PR517  -  [R_0402]  168.89 101.33 0 bottom
PR601  -  [R_0402]  48.21 70.78 180 bottom
PR602  -  [R0402_0OHM]  49.7 73.64 90 bottom
PR603  -  [R0402_0OHM]  47.33 73.41 90 bottom
PR604  -  [R_0402]  48.21 71.67 180 bottom
PR605  -  [R_0402]  48.21 72.56 180 bottom
PR606  -  [R0402_0OHM]  75.21 91.26 90 bottom
PR608  -  [R_0402]  48.2 73.53 180 top
PR610  -  [R_0402]  49 67.11 0 top
PR611  -  [R_0402]  48.2 74.42 180 top
PR612  -  [R_0402]  47.31 69.92 0 top
PR613  -  [R_0402]  49.46 69.79 270 bottom
PR614  -  [R0402_0OHM]  47.33 69.01 0 top
PR615  -  [R_0402]  58.23 69.39 270 top
PR616  -  [R0402_0OHM]  47.32 68.08 0 top
PR617  -  [R_0402]  52.5 69.41 270 bottom
PR618  -  [R_0402]  47.28 70.86 0 top
PR619  -  [R_0603]  73.03 87.85 180 top
PR620  -  [R0402_0OHM]  47.12 67.02 0 top
PR621  -  [R_0402]  50.79 65.32 90 top
PR622  -  [R_0402]  49.9 65.32 90 top
PR623  -  [R_0402]  47.37 66.13 0 top
PR624  -  [R_0603]  82.93 87.19 90 top
PR625  -  [R0402_0OHM]  47.28 71.74 0 top
PR626  -  [R_0402]  47.28 72.64 0 top
PR627  -  [R_1206]  80.52 89.38 180 top
PR628  -  [R_0402]  71.07 70.78 0 top
PR629  -  [R_0402]  54.61 69.44 0 bottom
PR630  -  [R_0402]  51.5 74.67 180 bottom
PR631  -  [R_0402]  68.22 71.1 0 top
PR632  -  [R_0402]  52.81 65.33 0 top
PR633  -  [R_0402]  51.78 67 270 bottom
PR634  -  [R_0402]  56.11 67.04 270 top
PR635  -  [R_0402]  57.03 70.22 90 top
PR636  -  [R_0402]  50.29 76.24 90 top
PR638  -  [R_0402]  52.82 66.21 90 top
PR639  -  [R_0402]  54.78 72.09 0 bottom
PR640  -  [R_0402]  57.83 75.56 0 top
PR641  -  [R_0402]  51.25 78.03 180 top
PR642  -  [R_0402]  82.22 91.12 0 bottom
PR643  -  [R_0402]  50.28 77.22 270 bottom
PR644  -  [R_0402]  57.83 76.45 0 top
PR645  -  [R_0402]  58.8 72 180 top
PR646  -  [R_0402]  54.15 76.31 90 top
PR647  -  [R_0402]  61.01 69.31 90 top
PR648  -  [R_0402]  57.01 72.9 270 top
PR649  -  [R_0402]  53.29 76.68 180 top
PR650  -  [R_0402]  57.9 71.08 0 top
PR651  -  [R_0402]  54.15 74.62 270 bottom
PR652  -  [R_0402]  55.04 76.31 90 top
PR653  -  [R_0402]  57.85 73.78 180 bottom
PR654  -  [R_0402]  48.49 77.21 270 bottom
PR656  -  [R_0402]  56.94 74.67 0 bottom
PR657  -  [R_0402]  79 80.73 180 top
PR658  -  [R_0402]  49.98 67.04 0 bottom
PR659  -  [R0402_0OHM]  77.13 83.91 0 top
PR660  -  [R_0603]  75.21 76.35 90 top
PR661  -  [R_0603]  77.7 81.79 0 top
PR662  -  [R_0402]  77.62 78.64 270 top
PR663  -  [R_1206]  71.82 85.65 180 top
PR664  -  [R0402_0OHM]  61.36 68.98 180 bottom
PR665  -  [R_0603]  54.66 66.29 0 bottom
PR666  -  [R_0402]  68.21 67.25 90 top
PR667  -  [R_0603]  67.11 66.87 270 top
PR668  -  [R_0603]  69.24 65.47 270 top
PR669  -  [R_1206]  68.26 61.18 180 bottom
PR670  -  [R_0402]  70.47 65.03 270 top
PR671  -  [R0402_0OHM]  69.79 76.93 180 bottom
PR672  -  [R_0603]  62.77 73.94 0 top
PR673  -  [R_0402]  76.8 73.39 270 top
PR674  -  [R_0603]  75.15 72.73 90 top
PR675  -  [R_0603]  78.08 74.09 270 top
PR676  -  [R_1206]  70.91 74.87 270 top
PR677  -  [R_0402]  77.94 71.76 270 top
PR678  -  [R_0402]  51.86 65.24 270 bottom
PR679  -  [R0402_0OHM]  72.06 86.44 180 bottom
PR680  -  [R_0402]  65.78 76.88 0 bottom
PR681  -  [R_0402]  57.63 68.97 0 bottom
PR901  -  [R_1206_4P-D]  49.63 87.04 270 bottom
PR909  -  [R_0402]  56.52 88.46 0 bottom
PR910  -  [R_0402]  58.73 87.47 0 bottom
PR914  -  [R0603_0OHM]  61.62 87.19 90 bottom
PR915  -  [R_0402]  64.93 89.19 0 bottom
PR916  -  [R_0805]  56.1 90.01 0 top
PR917  -  [R_1206_4P-D]  204.85 43.17 270 bottom
PR918  -  [R_0402]  59.63 99.24 0 bottom
PR919  -  [R_0402]  59.25 90.63 90 top
PR920  -  [R0402_0OHM]  56.09 92.68 0 top
PR921  -  [R_0603]  65.48 90.27 0 bottom
PR922  -  [R0402_0OHM]  56.1 93.57 0 top
PR923  -  [R_1206]  55.87 88.17 180 top
PR924  -  [R_1206]  61.01 81.75 270 top
PR925  -  [R_0402]  59.63 98.35 0 bottom
PR926  -  [R0402_0OHM]  58.68 95.85 270 top
PR927  -  [R_0402]  61.29 103.28 180 bottom
PR928  -  [R0402_0OHM]  56.04 94.4 0 bottom
PR929  -  [R0402_0OHM]  64.93 92.54 0 bottom
PR930  -  [R_0402]  56.05 96.2 90 bottom
PR931  -  [R_0402]  56.04 95.29 0 bottom
PR932  -  [R_0402]  58.93 96.12 90 bottom
PR933  -  [R_0402]  58.04 97.38 270 bottom
PR934  -  [R0402_0OHM]  61.56 96.06 90 bottom
PR935  -  [R0402_0OHM]  59.6 95.69 90 top
PR936  -  [R0402_0OHM]  62.35 95.62 90 top
PR937  -  [R_0402]  65.61 96.38 0 bottom
PR938  -  [R_0402]  65.61 97.28 0 bottom
PR939  -  [R0402_0OHM]  28.74 71.17 90 top
PR940  -  [R_0402]  63.85 96.92 270 bottom
PR941  -  [R0402_0OHM]  27.15 73.73 90 top
PR942  -  [R0402_0OHM]  29.64 71.15 90 top
PR943  -  [R0603_0OHM]  56.09 90.38 0 bottom
PR944  -  [R_0402]  55.22 93.54 270 bottom
PR945  -  [R_0402]  56.09 92.63 90 bottom
PR946  -  [R0402_0OHM]  33.75 73.42 270 top
PR947  -  [R0402_0OHM]  60.52 95.68 90 top
PR948  -  [R_0402]  62.36 94.33 180 top
PR949  -  [R0402_0OHM]  59.69 94.84 0 top
PR950  -  [R_0402]  28.37 75.52 0 top
PR951  -  [R0402_0OHM]  57.28 96.87 0 top
PR953  -  [R_0402]  33.75 71.68 270 top
PR960  -  [R0402_0OHM]  59.18 93.33 270 top
PR1201  -  [R_0402]  38.78 66.91 90 top
PR1202  -  [R_0402]  45.83 80.4 0 top
PR1203  -  [R_0402]  37.42 70.02 180 bottom
PR1205  -  [R_0402]  45.06 104.97 270 top
PR1206  -  [R_0402]  35.31 66.9 90 top
PR1207  -  [R_0402]  53.79 96.66 0 top
PR1208  -  [R_0402]  36.19 66.91 90 top
PR1209  -  [R_0402]  46.73 81.29 180 top
PR1210  -  [R_0402]  49.34 81.28 90 top
PR1211  -  [R0402_0OHM]  49.35 80.43 270 top
PR1212  -  [R_0402]  44.17 104.96 270 top
PR1213  -  [R_0402]  55.67 96.28 90 top
PR1214  -  [R_0402]  44.04 85.06 180 top
PR1215  -  [R0402_0OHM]  48.49 80.45 270 top
PR1216  -  [R0402_0OHM]  46.64 75.52 0 top
PR1217  -  [R_0402]  37.05 67.82 270 top
PR1218  -  [R0402_0OHM]  44.04 84.2 180 top
PR1219  -  [R_0402]  39.62 67.8 0 top
PR1220  -  [R0402_0OHM]  40.47 97 180 top
PR1221  -  [R0402_0OHM]  46.61 83.53 90 top
PR1222  -  [R_0402]  40.46 95.92 180 top
PR1223  -  [R0402_0OHM]  44.16 80.41 180 top
PR1224  -  [R_0402]  47.5 84.42 270 top
PR1225  -  [R0402_0OHM]  48.39 84.42 270 top
PR1226  -  [R_0402]  49.41 84.42 270 top
PR1227  -  [R_0402]  25.81 99.03 270 bottom
PR1228  -  [R_0402]  53.96 104.99 90 top
PR1229  -  [R_0402]  53.06 106.75 0 top
PR1230  -  [R_0402]  48.26 91.41 90 top
PR1231  -  [R_0402]  34.55 94.47 270 top
PR1232  -  [R_0402]  42.29 87.09 180 top
PR1233  -  [R_0402]  41.59 94.02 270 top
PR1234  -  [R_0402]  40.24 88.03 270 top
PR1235  -  [R_0402]  43.21 90.69 0 top
PR1236  -  [R_0402]  45.45 70 180 bottom
PR1237  -  [R_0402]  36.45 71.47 0 bottom
PR1238  -  [R0402_0OHM]  40.85 76.26 180 top
PR1239  -  [R_0402]  40.92 69.37 180 bottom
PR1240  -  [R_0402]  40.9 75.28 180 top
PR1241  -  [R0402_0OHM]  46.1 88.26 90 top
PR1242  -  [R0402_0OHM]  39.8 95.03 0 top
PR1243  -  [R0402_0OHM]  41.78 72.31 0 bottom
PR1244  -  [R0402_0OHM]  39.35 88.44 90 top
PR1245  -  [R0402_0OHM]  37.78 93.05 90 top
PR1246  -  [R_0402]  40.99 70.31 180 bottom
PR1247  -  [R_0402]  39.16 72.12 270 bottom
PR1248  -  [R_0402]  43.49 73.44 0 bottom
PR1249  -  [R_0402]  42.66 73.41 90 bottom
PR1250  -  [R0402_0OHM]  43.49 74.3 0 bottom
PR1251  -  [R_0402]  38.69 99.65 180 top
PR1252  -  [R_0402]  37.77 98.77 0 top
PR1253  -  [R_0402]  42.73 98.31 180 top
PR1254  -  [R_0402]  47.58 76.68 270 bottom
PR1255  -  [R_0402]  52.45 104.11 0 top
PR1257  -  [R0402_0OHM]  44.33 96.49 270 top
PR1258  -  [R_0402]  46.99 88.26 90 top
PR1259  -  [R_0402]  44.07 88.87 90 top
PR1260  -  [R_0402]  40.97 91.53 270 top
PR1261  -  [R_0402]  40.24 89.78 270 top
PR1301  -  [R0402_0OHM]  44.59 55.87 0 top
PR1302  -  [R_0402]  44.58 53.24 0 top
PR1303  -  [R0402_0OHM]  44.58 54.13 0 top
PR1304  -  [R_0402]  45.51 56.74 180 top
PR1305  -  [R_0603]  53.35 56.62 270 top
PR1306  -  [R_0402]  49.2 62.49 270 top
PR1307  -  [R_0402]  48.31 62.35 270 top
PR1308  -  [R_0402]  55.27 61.66 180 top
PR1309  -  [R_0402]  50.17 61.6 90 top
PR1310  -  [R_0402]  47.36 61.46 90 top
PR1311  -  [R_0402]  52.9 61.66 90 top
PR1312  -  [R_0402]  52.01 61.66 90 top
PR1313  -  [R_0402]  44.02 41.97 0 top
PR1314  -  [R0402_0OHM]  43.11 40.81 0 top
PR1315  -  [R0402_0OHM]  44.01 45.47 0 top
PR1316  -  [R_0402]  44.93 42.83 180 top
PR1317  -  [R_0402]  46.78 51.35 270 top
PR1318  -  [R_0402]  45.89 51.35 270 top
PR1319  -  [R_0603]  52 45.61 270 top
PR1320  -  [R_0402]  47.67 50.46 90 top
PR1321  -  [R_0402]  45 50.46 90 top
PR1322  -  [R_0402]  51.86 50.53 180 top
PR1323  -  [R_0402]  50 50.54 90 top
PR1324  -  [R_0402]  47.64 52.27 0 top
PR1325  -  [R_0402]  44.59 55.01 0 top
PR1326  -  [R_0402]  44.01 44.58 0 top
PRP1  -  [RP_0804_8P4R]  211.46 28.8 90 top
PT1  -  [TPC12]  46.04 73.51 180 bottom
PU1  -  [TC7SH08FU_SSOP5]  31.02 111.03 270 top
PU2  -  [AP2204RA-3P3TRG1_SOT89-3]  41.51 67.91 0 bottom
PU100  -  [SY8288BRAC_QFN20_3X3]  233.73 28.43 270 bottom
PU102  -  [SY8288CRAC_QFN20_3X3]  36.76 46.89 180 bottom
PU200  -  [SY8210AQVC_QFN19_4X3]  36.91 36.57 180 bottom
PU301  -  [SYX196DQNC_QFN10_3X3]  186.16 98.78 90 bottom
PU401  -  [SY8057QDC_QFN16_3X3]  184.71 109.66 0 bottom
PU402  -  [SY8057QDC_QFN16_3X3]  173.19 109.82 90 bottom
PU501  -  [RT8097ALGE_SOT23-6]  165.11 100.51 90 bottom
PU503  -  [AP7361C-FGE-7_U-DFN3030-8_3X3]  195.51 24.15 270 top
PU602  -  [ISL62883CHRTZ-T_TQFN40_5X5-S]  50.79 69.08 0 top
PU610  -  [CSD97374CQ4M_SON8_3P5X4P5]  76.3 82.61 180 top
PU612  -  [CSD97374CQ4M_SON8_3P5X4P5]  69.28 75.6 270 bottom
PU613  -  [CSD97374CQ4M_SON8_3P5X4P5]  61.09 67.6 270 bottom
PU614  -  [ISL95808HRZ-TS2378_DFN8_2X2-S]  71.6 89.91 0 bottom
PU901  -  [ISL88738HRTZ-T_TQFN32_4X4]  63.62 93.42 180 bottom
PU903  -  [TC7SH08FU_SSOP5]  30.69 72.66 270 top
PU1200  -  [TC7SH08FU_SSOP5]  49.13 78.47 180 top
PU1201  -  [LM393DGKR_VSSOP8]  38.74 69.44 90 top
PU1301  -  [SY8057QDC_QFN16_3X3]  51.86 57.79 180 top
PU1302  -  [SY8057QDC_QFN16_3X3]  50.28 46.81 180 top
QC2  -  [DMN65D8LDW-7_SOT363-6]  149.89 81.54 90 top
QE2  -  [DMN65D8LDW-7_SOT363-6]  282.75 29.19 0 top
QE3  -  [MMBT3904WT1G_SC70-3]  132.07 77 90 top
QE4  -  [MMBT3904WT1G_SC70-3]  241.25 37.99 270 bottom
QE5  -  [MMBT3904WT1G_SC70-3]  293.5 36.88 270 bottom
QE6  -  [MMBT3904WT1G_SC70-3]  83.14 92.83 90 bottom
QE7  -  [MMBT3904WT1G_SC70-3]  198.8 41.9 0 bottom
QE11  -  [L2N7002WT1G_SC-70-3]  244.22 36.06 90 bottom
QE12  -  [L2N7002WT1G_SC-70-3]  255.01 37.49 270 top
QE13  -  [DMN65D8LDW-7_SOT363-6]  257 83.18 0 top
QL1  -  [DMN65D8LDW-7_SOT363-6]  298.37 79.84 90 top
QL2  -  [DMN65D8LDW-7_SOT363-6]  293.48 81.12 270 top
QR1  -  [L2N7002WT1G_SC-70-3]  310.62 49.22 90 top
QT1  -  [DMN66D0LDW-7_SOT363-6]  39.76 65.16 270 bottom
QV1  -  [AO6405_TSOP6]  57.7 108.58 270 top
QV2  -  [L2N7002WT1G_SC-70-3]  58.13 104.46 270 top
QV3  -  [DMN65D8LDW-7_SOT363-6]  22.05 70.15 180 bottom
QV4  -  [L2N7002WT1G_SC-70-3]  16.51 70.44 180 top
QV5  -  [L2N7002WT1G_SC-70-3]  15.67 74.25 90 top
QV7  -  [L2N7002WT1G_SC-70-3]  95.91 110.24 90 top
QV8  -  [LP2301ALT1G_SOT23-3]  97.22 114.86 180 top
QZ1  -  [LP2301ALT1G_SOT23-3]  60.61 111.65 90 top
QZ2  -  [DMN65D8LDW-7_SOT363-6]  312.98 4.25 180 top
QZ3  -  [DDTA114EUA-7-F_SOT323-3]  312.55 8.22 0 top
QZ7  -  [DMN65D8LDW-7_SOT363-6]  242.63 43.69 90 bottom
QZ9  -  [LP2301ALT1G_SOT23-3]  163.2 81.35 180 bottom
R274  -  [R0603_0OHM]  295.54 56.41 0 top
RA3  -  [R0603_0OHM]  302.51 37.93 90 top
RA5  -  [R_0402]  298.71 26.5 90 top
RA6  -  [R_0402]  299.6 26.45 90 top
RA7  -  [R_0402]  305.63 33.43 0 top
RA8  -  [R_0402]  305.63 34.32 0 top
RA9  -  [R_0402]  294.26 31.13 0 top
RA12  -  [R_0402]  293.63 26.98 90 top
RA13  -  [R_0402]  293.96 26.14 270 top
RA14  -  [R_0402]  294.26 33.62 0 top
RA17  -  [R_0402]  295.18 32.61 180 top
RA18  -  [R_0402]  293.19 38.4 270 top
RA35  -  [R0402_0OHM]  303.16 31.15 180 bottom
RA36  -  [R0402_0OHM]  302.47 15.56 225 top
RA37  -  [R0402_0OHM]  298.99 24.73 225 top
RA44  -  [R_0402]  305.63 29.81 0 top
RA45  -  [R_0402]  294.85 26.14 270 top
RA48  -  [R0402_0OHM]  291.38 38.91 270 top
RA50  -  [R_0402]  292.28 38.91 270 top
RA51  -  [R_0402]  294.52 26.98 90 top
RA52  -  [R_0402]  294.26 34.58 0 top
RA53  -  [R_0402]  302.47 25.19 270 top
RA54  -  [R0402_0OHM]  301.56 25 270 top
RA55  -  [R0402_0OHM]  303.68 16.12 0 top
RA56  -  [R0402_0OHM]  303.66 14.46 0 top
RA57  -  [R_0402]  305.63 32.54 0 top
RA58  -  [R_0402]  305.63 31.65 0 top
RA59  -  [R_0402]  290.63 28.31 0 top
RA60  -  [R_0402]  291.57 29.27 180 top
RA61  -  [R_0402]  292.46 36.36 180 top
RC1  -  [R_0402]  140.26 81 180 top
RC2  -  [R_0402]  115.33 84.15 0 top
RC3  -  [R_0402]  135.37 98.77 90 top
RC4  -  [R_0402]  150.43 69.54 270 bottom
RC5  -  [R_0402]  133.77 60.09 270 top
RC6  -  [R_0402]  134.66 60.09 270 top
RC7  -  [R_0402]  136.93 59.63 270 top
RC10  -  [R_0402]  150.41 64.32 270 bottom
RC11  -  [R_0402]  150.41 66.09 270 bottom
RC12  -  [R_0402]  148.5 83.56 90 bottom
RC13  -  [R_0402]  144.66 54.58 180 top
RC14  -  [R_0402]  149.39 83.56 90 bottom
RC15  -  [R_0402]  150.13 80.23 180 top
RC16  -  [R_0402]  147.58 61.18 180 top
RC17  -  [R_0402]  150.13 79.34 180 top
RC19  -  [R_0402]  277.62 99.46 90 top
RC20  -  [R_0402]  273.56 102.03 270 top
RC21  -  [R_0402]  142.11 61.33 270 top
RC22  -  [R_0402]  149.35 61.18 180 top
RC23  -  [R_0402]  144.6 78.67 0 top
RC25  -  [R_0402]  148 78.59 0 bottom
RC27  -  [R_0402]  144.91 60.8 270 top
RC28  -  [R_0402]  158.21 76.81 0 bottom
RC29  -  [R_0402]  177.48 87.2 90 bottom
RC30  -  [R_0402]  173.62 79.66 180 bottom
RC31  -  [R_0402]  173.62 78.77 180 bottom
RC32  -  [R_0402]  179.91 71.21 180 bottom
RC33  -  [R0402_0OHM]  177.21 71.28 270 bottom
RC34  -  [R0402_0OHM]  176.27 71.27 270 bottom
RC35  -  [R0402_0OHM]  175.01 71.28 270 bottom
RC36  -  [R0402_0OHM]  173.92 71.29 270 bottom
RC37  -  [R0402_0OHM]  189.28 91.95 270 bottom
RC38  -  [R0402_0OHM]  172.9 71.32 270 bottom
RC39  -  [R_0402]  190.16 88.42 180 bottom
RC40  -  [R0402_0OHM]  171.83 71.29 270 bottom
RC41  -  [R0402_0OHM]  170.86 70.4 90 bottom
RC42  -  [R_0402]  189.3 85.72 270 bottom
RC43  -  [R_0402]  190.15 82.28 180 bottom
RC44  -  [R_0402]  142.69 77.33 0 top
RC45  -  [R_0402]  142.98 84.29 0 top
RC46  -  [R_0402]  124.88 95.68 180 bottom
RC47  -  [R_0402]  166.36 55.77 270 top
RC48  -  [R_0402]  137.92 59.66 270 top
RC50  -  [R_0402]  168.52 56.67 0 top
RC51  -  [R_0402]  168.52 57.56 0 top
RC52  -  [R_0402]  133.8 81.26 90 top
RC54  -  [R_0402]  151.48 74.18 0 top
RC56  -  [R_0402]  140.42 58.87 270 top
RC57  -  [R_0402]  141.82 59.12 270 top
RC59  -  [R_0402]  169.04 54.83 180 top
RC60  -  [R_0402]  177.17 91.85 180 bottom
RC62  -  [R0402_0OHM]  177.17 90.09 270 bottom
RC65  -  [R_0402]  171.96 92.42 270 bottom
RC67  -  [R_0402]  171.87 49.55 90 top
RC68  -  [R_0402]  170.93 48.35 0 top
RC69  -  [R_0402]  150.17 61.18 0 top
RC71  -  [R_0402]  105.97 96.15 0 bottom
RC72  -  [R_0402]  174.71 54.76 270 top
RC73  -  [R_0402]  164.52 69.77 180 top
RC74  -  [R_0402]  160.25 61.27 270 top
RC75  -  [R_0402]  138.69 54.58 0 top
RC77  -  [R_0402]  99.94 95.24 270 bottom
RC78  -  [R_0402]  104.4 94.46 270 bottom
RC79  -  [R_0402]  108.84 97.63 180 bottom
RC80  -  [R_0402]  108.64 96.32 180 bottom
RC81  -  [R_0402]  111.84 93.71 90 bottom
RC82  -  [R_0402]  113.29 95.98 90 bottom
RC83  -  [R_0402]  103.86 97.15 90 bottom
RC84  -  [R_0402]  103.84 96.26 270 bottom
RC86  -  [R_0402]  114.56 93.53 90 bottom
RC87  -  [R_0402]  110.88 95.49 0 bottom
RC88  -  [R_0402]  143.77 55.47 0 top
RC89  -  [R_0402]  144.69 58.13 270 top
RC90  -  [R_0402]  107.24 83.57 180 top
RC91  -  [R_0402]  108.93 83.7 0 top
RC92  -  [R_0402]  137.96 55.68 90 top
RC93  -  [R_0402]  137.07 55.68 90 top
RC94  -  [R_0402]  134.94 54.18 90 top
RC95  -  [R_0402]  133.61 55.07 90 top
RC96  -  [R_0402]  142.02 78.76 180 top
RC109  -  [R_0402]  98.11 94.32 90 bottom
RC110  -  [R_0402]  101.95 94.02 90 bottom
RC112  -  [R_0402]  100.98 94.01 90 bottom
RC113  -  [R_0402]  102.9 94.03 90 bottom
RC114  -  [R_0402]  111.21 84.2 0 top
RC115  -  [R_0402]  153.49 102.52 180 top
RC120  -  [R_0402]  105.99 95.25 0 bottom
RC121  -  [R_0402]  84.32 98.65 90 bottom
RC122  -  [R_0402]  83.43 98.65 90 bottom
RC123  -  [R_0402]  105.03 97.01 90 bottom
RC124  -  [R_0402]  78.74 99.93 180 bottom
RC126  -  [R_0402]  75.82 99.93 180 bottom
RC128  -  [R_0402]  73.08 98.14 90 bottom
RC129  -  [R_0402]  73.97 98.14 90 bottom
RC130  -  [R_0402]  112.37 96.56 90 bottom
RC131  -  [R_0402]  60.71 100.68 90 top
RC132  -  [R_0402]  74.91 99.04 0 bottom
RC133  -  [R_0402]  72.2 97.95 180 bottom
RC134  -  [R_0402]  59.82 100.3 90 top
RC135  -  [R_0402]  64.65 103.6 90 top
RC136  -  [R_0402]  63.5 97.88 270 top
RC137  -  [R_0402]  116.54 100.6 270 bottom
RC138  -  [R_0402]  88.19 100.07 270 bottom
RC139  -  [R_0402]  71.5 100.05 180 bottom
RC140  -  [R_0402]  127.13 90.99 0 bottom
RC141  -  [R_0402]  126.28 90.98 180 bottom
RC143  -  [R0603_0OHM]  131.35 95.52 180 top
RC152  -  [R_0402]  106.9 93.47 90 bottom
RC153  -  [R_0402]  107.8 93.47 90 bottom
RC157  -  [R_0402]  106 93.47 90 bottom
RC161  -  [R_0402]  99.95 82.71 270 bottom
RC163  -  [R_0402]  99.88 84.08 180 bottom
RC165  -  [R_0402]  130.85 72.64 180 top
RC166  -  [R_0402]  133.38 83.38 0 top
RC167  -  [R_0402]  132.6 72.64 180 top
RC168  -  [R_0402]  131.47 84.15 0 top
RC169  -  [R0603_0OHM]  166.34 88.67 180 top
RC170  -  [R0402_0OHM]  130.39 100.39 270 top
RC171  -  [R0402_0OHM]  136.41 99.93 270 bottom
RC173  -  [R0402_0OHM]  135.51 99.94 270 bottom
RC175  -  [R_0402]  146.19 79.62 180 top
RC176  -  [R_0402]  144.73 82.28 0 top
RC177  -  [R_0402]  144.73 81.4 0 top
RC178  -  [R_0402]  146.19 80.51 180 top
RC183  -  [R_0402]  161.14 61.27 270 top
RC184  -  [R_0402]  142.41 72.82 180 top
RC186  -  [R_0402]  162.05 61.31 270 top
RC187  -  [R_0402]  135.78 55.97 180 top
RC189  -  [R_0402]  167.24 55.77 270 top
RC190  -  [R_0402]  157.8 71.89 90 bottom
RC211  -  [R_0402]  164.34 59.66 90 top
RC212  -  [R0402_0OHM]  166.37 64.48 270 top
RC214  -  [R0402_0OHM]  173.95 52.85 180 top
RC215  -  [R_0402]  139.5 56.41 270 top
RC216  -  [R0603_0OHM]  112.77 100.17 0 bottom
RC217  -  [R_0402]  75.82 98.15 180 bottom
RC218  -  [R_0402]  74.92 97.15 270 bottom
RC219  -  [R_0402]  75.81 97.15 270 bottom
RC220  -  [R_0402]  140.49 55.21 0 top
RC221  -  [R0402_0OHM]  238.56 47.72 180 bottom
RC222  -  [R_0402]  238.56 46.83 180 bottom
RC223  -  [R_0402]  135.83 54.18 90 top
RC224  -  [R_0402]  151.81 98.51 270 bottom
RC225  -  [R_0402]  148.33 102.52 90 bottom
RC227  -  [R_0402]  149.22 102.52 90 bottom
RC228  -  [R0402_0OHM]  60.71 99.15 180 top
RC229  -  [R0402_0OHM]  63.38 103.73 90 top
RC230  -  [R0402_0OHM]  66.04 103.6 90 top
RC231  -  [R0402_0OHM]  125.08 72.96 0 top
RC232  -  [R0603_0OHM]  122.81 101.19 270 bottom
RC234  -  [R_0402]  154.15 72.91 180 bottom
RC235  -  [R0402_0OHM]  150.55 73.11 0 bottom
RC237  -  [R_0402]  162.94 61.31 270 top
RC239  -  [R_0402]  82.54 99.09 90 bottom
RC240  -  [R_0402]  81.65 99.09 90 bottom
RC241  -  [R_0402]  78.73 97.59 270 bottom
RC243  -  [R_0402]  172.93 54.76 270 top
RC244  -  [R0402_0OHM]  177.2 90.96 180 bottom
RC267  -  [R_0402]  148.91 81.32 0 bottom
RC268  -  [R_0402]  148.89 80.43 0 bottom
RC272  -  [R_0402]  150.19 96.47 180 bottom
RC278  -  [R_0402]  152.21 83.6 180 bottom
RC279  -  [R_0402]  158.7 71.89 90 bottom
RC282  -  [R_0402]  145.32 72.17 270 top
RC283  -  [R_0402]  149.16 75.58 90 top
RC287  -  [R_0402]  110.09 93.71 90 bottom
RC288  -  [R_0402]  153.93 94.46 0 top
RC290  -  [R0402_0OHM]  152.71 97.6 90 bottom
RC291  -  [R_0402]  150.93 97.6 90 bottom
RC292  -  [R_0402]  153.22 77.6 180 bottom
RC295  -  [R0402_0OHM]  125.74 95.68 0 bottom
RC296  -  [R0402_0OHM]  151.06 73.29 180 top
RC297  -  [R_0402]  119.65 84.19 0 top
RC298  -  [R_0402]  121.38 84.21 0 top
RC299  -  [R0603_0OHM]  139.7 102.17 270 bottom
RC300  -  [R0402_0OHM]  141.07 99.02 270 top
RC301  -  [R0402_0OHM]  148.68 95.28 180 top
RC302  -  [R0402_0OHM]  141.96 99.02 270 top
RC303  -  [R0402_0OHM]  136.52 100.18 270 top
RC304  -  [R0402_0OHM]  145.7 75.76 180 top
RC305  -  [R0402_0OHM]  139.88 75.31 180 top
RC306  -  [R0402_0OHM]  148.52 73.73 180 top
RC307  -  [R0402_0OHM]  148.27 77.32 270 top
RC308  -  [R0402_0OHM]  145.69 77.59 180 top
RC309  -  [R0603_0OHM]  146.99 99.29 270 top
RC310  -  [R0603_0OHM]  145.72 99.29 270 top
RC311  -  [R_0402]  146.69 71.6 0 top
RC313  -  [R_0402]  145.7 76.69 180 top
RC316  -  [R_0402]  174.49 78.77 0 bottom
RC317  -  [R_0402]  153.65 73.8 180 bottom
RC318  -  [R_0402]  187.54 25.94 180 top
RC319  -  [R_0402]  187.54 26.84 180 top
RC323  -  [R_0402]  170.92 51.39 270 top
RC324  -  [R_0402]  132.5 80.49 90 top
RC325  -  [R0402_0OHM]  172.88 91.58 0 bottom
RC328  -  [R0402_0OHM]  110.96 93.7 90 bottom
RC330  -  [R_0402]  154.32 75.55 270 bottom
RC331  -  [R_0402]  154.66 77.29 0 bottom
RC337  -  [R0402_0OHM]  145.53 73.49 90 top
RC338  -  [R_0402]  144.43 71.72 180 top
RC344  -  [R_0402]  170.08 48.35 180 top
RC345  -  [R_0402]  148.08 100.04 270 top
RC346  -  [R_0402]  153.49 101.63 180 top
RC347  -  [R_0402]  150.85 78.23 270 top
RC348  -  [R_0402]  149.96 78.23 270 top
RC349  -  [R_0402]  151.34 69.51 270 bottom
RC362  -  [R_0402]  165.67 71.01 90 bottom
RC363  -  [R_0402]  164.7 71 90 bottom
RC366  -  [R_0402]  179.38 59.7 0 top
RC367  -  [R_0402]  179.38 61.46 0 top
RC368  -  [R_0402]  179.38 60.59 0 top
RC369  -  [R_0402]  179.39 62.36 0 top
RC371  -  [R_0402]  143.19 96.2 90 bottom
RC372  -  [R_0402]  144.11 96.2 90 bottom
RC373  -  [R0402_0OHM]  169.01 55.75 180 top
RC374  -  [R0402_0OHM]  165.46 56.86 0 top
RC375  -  [R0402_0OHM]  167.64 57.58 270 top
RC376  -  [R0402_0OHM]  172.49 56.74 180 top
RC377  -  [R0402_0OHM]  168.59 59.35 270 top
RC378  -  [R0402_0OHM]  156.89 71.02 0 bottom
RC387  -  [R_0402]  164.49 70.68 180 top
RC400  -  [R_0402]  163.01 86.51 0 top
RC401  -  [R_0402]  163.01 85.55 0 top
RC402  -  [R_0402]  151.46 74.26 180 bottom
RC403  -  [R_0402]  154.67 76.4 0 bottom
RC405  -  [R_0402]  150.42 77.63 0 bottom
RC407  -  [R_0402]  177.87 83.34 0 bottom
RC408  -  [R_0402]  177.99 82.26 0 bottom
RC409  -  [R_0402]  178.82 80.23 90 bottom
RC410  -  [R_0402]  180.72 79.6 0 bottom
RC411  -  [R_0402]  191.47 63.52 90 bottom
RC412  -  [R_0402]  149.51 85.41 90 bottom
RC413  -  [R_0402]  151.64 95.47 180 top
RC414  -  [R_0402]  176.66 62.71 180 top
RD4  -  [R_0402]  114.25 32.16 180 top
RD5  -  [R0402_0OHM]  112.09 29.03 180 top
RD6  -  [R_0402]  114.19 31.3 270 top
RD7  -  [R0402_0OHM]  113.31 30.38 90 top
RD8  -  [R_0402]  91.06 24.49 180 top
RD9  -  [R0402_0OHM]  90.15 25.37 0 top
RD10  -  [R0603_0OHM]  111.38 33.75 270 top
RD11  -  [R_0402]  136.72 28.16 180 top
RD12  -  [R0402_0OHM]  134.8 27.28 0 top
